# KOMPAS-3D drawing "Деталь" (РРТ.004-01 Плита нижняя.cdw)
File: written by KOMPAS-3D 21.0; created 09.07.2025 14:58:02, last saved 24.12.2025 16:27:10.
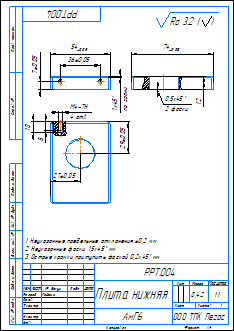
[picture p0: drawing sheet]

Sheet 1: A4, portrait

Document properties: Автор: User; Знак неуказанной шероховатости: 4; Параметр неуказанной шероховатости: Ra 3.2; Масса: 0.423013; Полное имя файла: ..\Модели КД\РРТ.004-01 Плита нижняя.m3d

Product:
- Part/product: Деталь
    Масса: 0.321259

Title block, sheet 1: Наименование: Плита нижняя; designation: РРТ.004; Материал: АмГ6; Масса: 0,42; Количество листов документа: 1; organisation: ООО ТПК Пегас; Форматы листов документа: A4; stored path: C:\Users\User\Desktop\Р-й Рот-р\Компас чертежи\Плита Моноблока _ Ручной Ротатор.cdw; Разработал: Гайсин

Views: Спереди 1, Спереди, Проекционный вид 3, Местный разрез 1, Проекционный вид 4
Referenced files in C:\Users\User\Desktop\Ручной ротатор КД\Модели КД\: Плита низ.m3d, РРТ.004-01 Плита нижняя.m3d, РРТ.004 Плита нижняя.m3d
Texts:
  пр грани
  Ra 3.2
  Ra 3.2 ( )
Dimensions and other numbers on the sheet: 36±0,05; 7±0,05; 54; 1; 0,5; 2 фаски; 74; 12; 8; 10; -7Н; 4; 4 отв; 27±0,05; 29±0,05; 1:1; 0,42

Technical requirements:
  Неуказанные предельные отклонения  0,2 мм
  Неуказанные фаски 1,5х45  мм
  Острые кромки притупить фаской 0,2х45  мм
